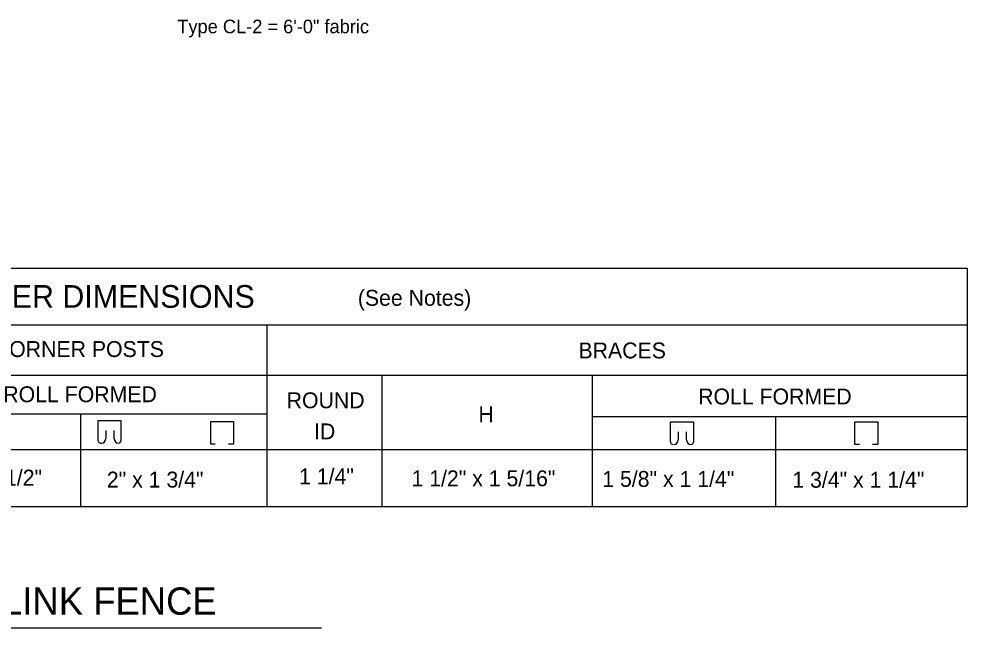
# Model space of a CAD drawing. Extents: x 6710407 to 6714861, y 1868090 to 1871317.
# Drawn here: x 6712386.6 to 6712804.1, y 1870012 to 1870280.4 of the extents above; entities that cross this region are included whole.
import ezdxf

# ---------------------------------------------------------------- set-up
doc = ezdxf.new("R2010")
doc.units = 0
doc.layers.add('Nongeo Data(60)', color=7, linetype='Continuous')

msp = doc.modelspace()

# ---------------------------------------------------------------- linework, layer by layer
at = {"layer": 'Nongeo Data(60)'}
for p, q in [((6712040.29, 1870170.62), (6712804.07, 1870170.62)), ((6712804.07, 1870170.62), (6712804.07, 1870065.62)), ((6712040.29, 1870145.62), (6712804.07, 1870145.62)), ((6712495.7, 1870145.62), (6712495.7, 1870065.62)), ((6712090.57, 1870123.43), (6712804.07, 1870123.43)), ((6712546.42, 1870123.43), (6712546.42, 1870065.62)), ((6712638.94, 1870123.43), (6712638.94, 1870065.62)), ((6712331.69, 1870106.43), (6712495.7, 1870106.43)), ((6712413.74, 1870106.49), (6712413.74, 1870065.62)), ((6712638.94, 1870105.3), (6712804.07, 1870105.3)), ((6712719.66, 1870105.3), (6712719.66, 1870065.62)), ((6712421.52, 1870094.54), (6712421.52, 1870103.54)), ((6712421.52, 1870103.54), (6712431.52, 1870103.54)), ((6712431.52, 1870103.54), (6712431.52, 1870094.54)), ((6712471.08, 1870093.09), (6712471.08, 1870103.09)), ((6712471.08, 1870103.09), (6712481.08, 1870103.09)), ((6712481.08, 1870103.09), (6712481.08, 1870093.09)), ((6712673.56, 1870093.93), (6712673.56, 1870102.93)), ((6712673.56, 1870102.93), (6712683.56, 1870102.93)), ((6712683.56, 1870102.93), (6712683.56, 1870093.93)), ((6712754.72, 1870092.85), (6712754.72, 1870102.85)), ((6712754.72, 1870102.85), (6712764.72, 1870102.85)), ((6712764.72, 1870102.85), (6712764.72, 1870092.85)), ((6712424.86, 1870099.05), (6712424.86, 1870095.54)), ((6712424.86, 1870099.05), (6712424.86, 1870095.54)), ((6712428.52, 1870095.54), (6712428.52, 1870099.05)), ((6712676.89, 1870098.45), (6712676.89, 1870094.93)), ((6712680.56, 1870094.93), (6712680.56, 1870098.45)), ((6712422.52, 1870093.54), (6712423.01, 1870093.54)), ((6712430.52, 1870093.54), (6712430.52, 1870093.54)), ((6712473.06, 1870093.09), (6712471.08, 1870093.09)), ((6712481.08, 1870093.09), (6712478.8, 1870093.09)), ((6712756.69, 1870092.85), (6712754.72, 1870092.85)), ((6712764.72, 1870092.85), (6712762.43, 1870092.85)), ((6712040.7, 1870090.62), (6712804.07, 1870090.62)), ((6712040.29, 1870065.62), (6712804.07, 1870065.62)), ((6712519.81, 1870012.03), (6712294.57, 1870012.03))]:
    msp.add_line(p, q, dxfattribs=at)
for centre, radius, start, end in [((6712422.52, 1870094.54), 1, 180, 270), ((6712422.86, 1870095.54), 2, 270, 0), ((6712422.86, 1870095.54), 2, 270, 0), ((6712430.52, 1870095.54), 2, 180, 270), ((6712430.52, 1870094.54), 1, 270, 0), ((6712674.56, 1870093.93), 1, 180, 270), ((6712674.89, 1870094.93), 2, 270, 0), ((6712682.56, 1870094.93), 2, 180, 270), ((6712682.56, 1870093.93), 1, 270, 0)]:
    msp.add_arc(centre, radius, start, end, dxfattribs=at)

# ---------------------------------------------------------------- texts
for s, height, p in [('Type CL-2 = 6\'-0" fabric', 6, (6712456.32, 1870274.06)), ('TYPICAL MEMBER DIMENSIONS    ', 10, (6712283.86, 1870153.12)), ('(See Notes)', 7, (6712535.81, 1870154.01)), ('END, LATCH & CORNER POSTS', 7, (6712308.43, 1870131.44)), ('BRACES', 7, (6712632.98, 1870130.83)), ('ROLL FORMED', 7, (6712379.7, 1870111.52)), ('ROLL FORMED', 7, (6712685.66, 1870110.55)), ('ROUND', 7, (6712504.47, 1870108.86)), ('H', 7, (6712588.92, 1870102.67)), ('ID', 7, (6712516.53, 1870095.17)), ('3 1/2" x 3 1/2"', 7, (6712338.61, 1870074.8)), ('2" x 1 3/4"', 7, (6712425.3, 1870073.93)), ('1 1/4"', 7, (6712509.94, 1870075.38)), ('1 1/2" x 1 5/16"', 7, (6712559.45, 1870074.49)), ('1 5/8" x 1 1/4"', 7, (6712643.45, 1870074.21)), ('1 3/4" x 1 1/4"', 7, (6712727.14, 1870073.86)), ('CHAIN LINK FENCE', 12, (6712324.77, 1870017.92))]:
    msp.add_text(s, height=height, dxfattribs=at).set_placement(p)

doc.saveas('drawing.dxf')
